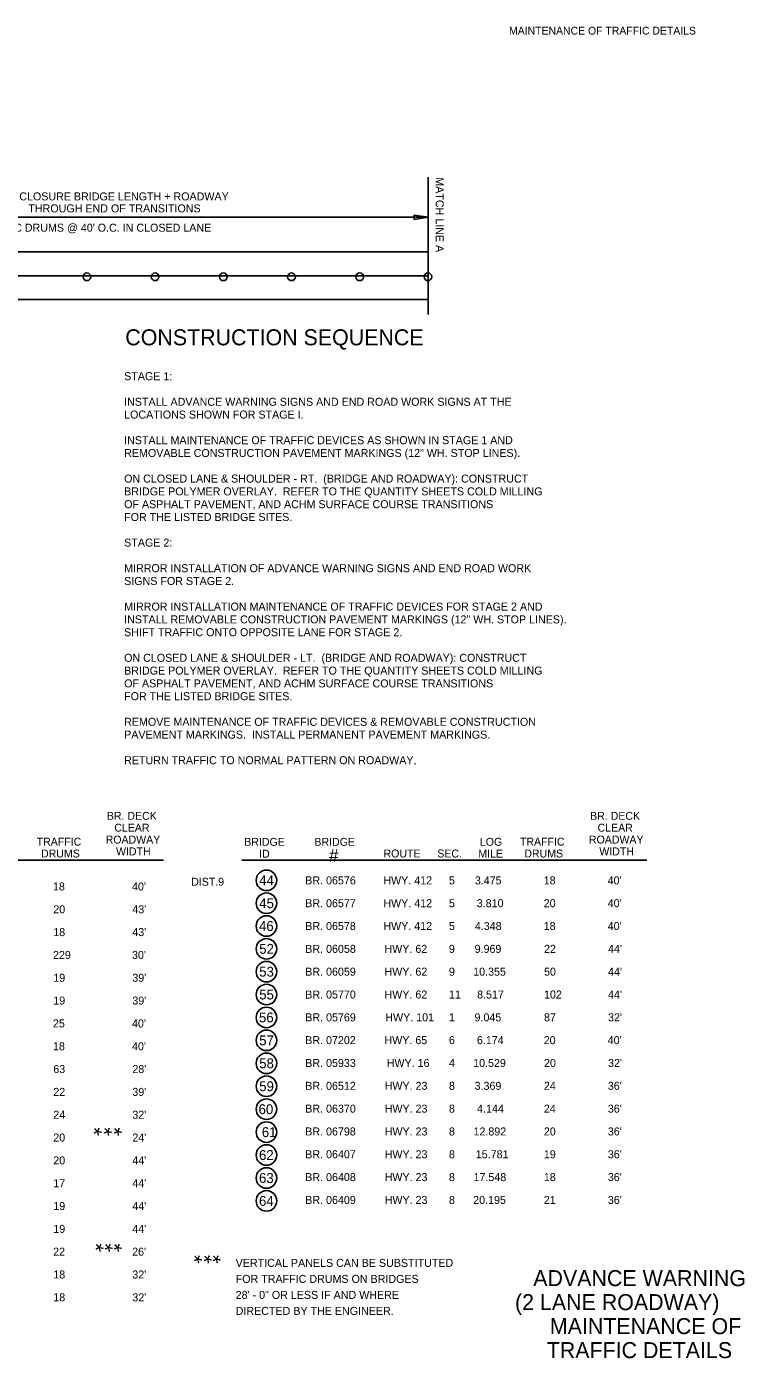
# Model space of a CAD drawing. Extents: x 1927831 to 1930787, y 596452 to 597699.
# Drawn here: x 1928872 to 1929411, y 596676 to 597675 of the extents above; entities that cross this region are included whole.
import ezdxf

# ---------------------------------------------------------------- set-up
doc = ezdxf.new("R2010")
doc.units = 0
for name, color, linetype in [('Default', 7, 'Continuous'), ('R_Border', 7, 'Continuous'), ('S_AREA_CALC', 7, 'Continuous')]:
    doc.layers.add(name, color=color, linetype=linetype)

msp = doc.modelspace()

# ---------------------------------------------------------------- linework, layer by layer
at = {"layer": 'Default'}
for p, q in [((1929173.7, 597561.58), (1929173.7, 597458.57)), ((1929173.7, 597531.57), (1928729.31, 597531.57)), ((1929163.15, 597529.98), (1929163.15, 597533.15)), ((1929163.15, 597533.15), (1929173.7, 597531.57)), ((1929173.7, 597531.57), (1929163.15, 597529.98)), ((1928044.85, 597505.58), (1929173.7, 597505.58)), ((1927908.3, 597487.79), (1929173.7, 597487.79)), ((1928044.85, 597470), (1929173.7, 597470))]:
    msp.add_line(p, q, dxfattribs=at)
for centre, radius in [((1928917.66, 597486.95), 2.88), ((1928968.83, 597486.95), 2.88), ((1929019.99, 597486.95), 2.88), ((1929071.15, 597486.95), 2.88), ((1929122.31, 597486.95), 2.88), ((1929173.48, 597486.95), 2.88), ((1929052.37, 597034.32), 7.71), ((1929052.37, 597017.2), 7.71), ((1929052.37, 597000.08), 7.71), ((1929052.37, 596982.96), 7.71), ((1929052.37, 596965.85), 7.71), ((1929052.37, 596948.73), 7.71), ((1929052.37, 596931.53), 7.71), ((1929052.37, 596914.33), 7.71), ((1929052.37, 596897.13), 7.71), ((1929052.37, 596879.93), 7.71), ((1929052.37, 596862.73), 7.71), ((1929052.37, 596845.53), 7.71), ((1929052.37, 596828.33), 7.71), ((1929052.37, 596811.13), 7.71), ((1929052.37, 596793.93), 7.71)]:
    msp.add_circle(centre, radius, dxfattribs=at)
at = {"layer": 'R_Border'}
for p, q in [((1928671.26, 597049.57), (1928975.19, 597049.57)), ((1929033.81, 597049.57), (1929337.74, 597049.57))]:
    msp.add_line(p, q, dxfattribs=at)

# ---------------------------------------------------------------- texts
at = {"layer": 'Default'}
for s, height, rotation, p in [('MATCH LINE A', 6, 270, (1929179.33, 597561.58)), ('LANE CLOSURE BRIDGE LENGTH + ROADWAY ', 5.9996, 360, (1928843.74, 597544.26)), ('THROUGH END OF TRANSITIONS', 5.9996, 360, (1928873.73, 597535.26)), ("TRAFFIC DRUMS @ 40' O.C. IN CLOSED LANE", 5.9996, 360, (1928835.01, 597520.77))]:
    msp.add_text(s, height=height, rotation=rotation, dxfattribs=at).set_placement(p)
at = {"layer": 'R_Border'}
for s, height, rotation, p in [('CONSTRUCTION SEQUENCE', 12, 360, (1928946.46, 597435.58)), ('STAGE 1:', 6, 360, (1928945.6, 597409.43)), ('INSTALL ADVANCE WARNING SIGNS AND END ROAD WORK SIGNS AT THE', 6, 360, (1928945.6, 597390.23)), ('LOCATIONS SHOWN FOR STAGE I.  ', 6, 360, (1928945.6, 597380.63)), ('INSTALL MAINTENANCE OF TRAFFIC DEVICES AS SHOWN IN STAGE 1 AND', 6, 360, (1928945.6, 597361.43)), ('REMOVABLE CONSTRUCTION PAVEMENT MARKINGS (12" WH. STOP LINES). ', 6, 360, (1928945.6, 597351.83)), ('ON CLOSED LANE & SHOULDER - RT.  (BRIDGE AND ROADWAY): CONSTRUCT', 6, 360, (1928945.6, 597332.63)), ('BRIDGE POLYMER OVERLAY.  REFER TO THE QUANTITY SHEETS COLD MILLING', 6, 360, (1928945.6, 597323.03)), ('OF ASPHALT PAVEMENT, AND ACHM SURFACE COURSE TRANSITIONS', 6, 360, (1928945.6, 597313.43)), ('FOR THE LISTED BRIDGE SITES.', 6, 360, (1928945.6, 597303.83)), ('STAGE 2:', 6, 360, (1928945.6, 597284.63)), ('MIRROR INSTALLATION OF ADVANCE WARNING SIGNS AND END ROAD WORK', 6, 360, (1928945.6, 597265.43)), ('SIGNS FOR STAGE 2.  ', 6, 360, (1928945.6, 597255.83)), ('MIRROR INSTALLATION MAINTENANCE OF TRAFFIC DEVICES FOR STAGE 2 AND', 6, 360, (1928945.6, 597236.63)), ('INSTALL REMOVABLE CONSTRUCTION PAVEMENT MARKINGS (12" WH. STOP LINES).', 6, 360, (1928945.6, 597227.03)), ('SHIFT TRAFFIC ONTO OPPOSITE LANE FOR STAGE 2.', 6, 360, (1928945.6, 597217.43)), ('ON CLOSED LANE & SHOULDER - LT.  (BRIDGE AND ROADWAY): CONSTRUCT', 6, 360, (1928945.6, 597198.23)), ('BRIDGE POLYMER OVERLAY.  REFER TO THE QUANTITY SHEETS COLD MILLING', 6, 360, (1928945.6, 597188.63)), ('OF ASPHALT PAVEMENT, AND ACHM SURFACE COURSE TRANSITIONS', 6, 360, (1928945.6, 597179.03)), ('FOR THE LISTED BRIDGE SITES.', 6, 360, (1928945.6, 597169.43)), ('REMOVE MAINTENANCE OF TRAFFIC DEVICES & REMOVABLE CONSTRUCTION', 6, 360, (1928945.6, 597150.23)), ('PAVEMENT MARKINGS.  INSTALL PERMANENT PAVEMENT MARKINGS.', 6, 360, (1928945.6, 597140.63)), ('RETURN TRAFFIC TO NORMAL PATTERN ON ROADWAY. ', 6, 360, (1928945.6, 597121.43)), ('BR. DECK ', 5.929, 360, (1928932.62, 597079.75)), ('BR. DECK ', 5.929, 360, (1929295.17, 597079.75)), ('CLEAR', 5.929, 360, (1928938.2, 597070.86)), ('CLEAR', 5.929, 360, (1929300.75, 597070.86)), ('TRAFFIC ', 5.929, 360, (1928879.98, 597060.4)), ('ROADWAY ', 5.929, 360, (1928931.73, 597061.96)), ('BRIDGE ', 5.929, 360, (1929035.7, 597060.24)), ('BRIDGE ', 5.929, 360, (1929088.33, 597060.24)), ('LOG', 5.929, 360, (1929212.52, 597060.28)), ('TRAFFIC ', 5.929, 360, (1929242.53, 597060.4)), ('ROADWAY ', 5.929, 360, (1929294.28, 597061.96)), ('DRUMS', 5.929, 360, (1928883.27, 597051.51)), ('WIDTH', 5.929, 360, (1928939.53, 597053.07)), ('ID', 5.929, 360, (1929046.88, 597051.35)), ('#', 9.5, 360, (1929099.32, 597048.38)), ('ROUTE', 5.929, 360, (1929140.18, 597051.51)), ('SEC.', 5.929, 360, (1929180.51, 597051.51)), ('MILE', 5.929, 360, (1929211.29, 597051.39)), ('DRUMS', 5.929, 360, (1929245.82, 597051.51)), ('WIDTH', 5.929, 360, (1929302.08, 597053.07)), ('DIST.9', 5.929, 360, (1928995.9, 597030.33)), ('44', 7.412, 360, (1929046.94, 597030.61)), ('BR. 06576', 6, 360, (1929081.46, 597031.32)), ('HWY. 412', 6, 360, (1929140.05, 597031.32)), ('5', 6, 360, (1929189.24, 597031.32)), ('3.475', 6, 360, (1929208.68, 597031.32)), ('18', 6, 360, (1929260.35, 597031.32)), ("40'", 6, 360, (1929308.35, 597031.32)), ('18', 6, 360, (1928892.21, 597026.76)), ("40'", 6, 360, (1928951.51, 597026.76)), ('20', 6, 360, (1928892.45, 597009.64)), ("43'", 6, 360, (1928951.74, 597009.64)), ('45', 7.412, 360, (1929046.94, 597013.49)), ('BR. 06577', 6, 360, (1929081.46, 597014.2)), ('HWY. 412', 6, 360, (1929140.05, 597014.2)), ('5', 6, 360, (1929189.24, 597014.2)), ('3.810', 6, 360, (1929210.12, 597014.2)), ('20', 6, 360, (1929260.35, 597014.2)), ("40'", 6, 360, (1929308.35, 597014.2)), ('18', 6, 360, (1928892.45, 596992.52)), ("43'", 6, 360, (1928951.74, 596992.52)), ('46', 7.412, 360, (1929046.74, 596996.38)), ('BR. 06578', 6, 360, (1929081.46, 596997.08)), ('HWY. 412', 6, 360, (1929140.05, 596997.08)), ('5', 6, 360, (1929189.24, 596997.08)), ('4.348', 6, 360, (1929208.68, 596997.08)), ('18', 6, 360, (1929260.35, 596997.08)), ("40'", 6, 360, (1929308.35, 596997.08)), ('52', 7.412, 360, (1929046.94, 596979.26)), ('BR. 06058', 6, 360, (1929081.46, 596979.96)), ('HWY. 62', 6, 360, (1929140.9, 596979.96)), ('9', 6, 360, (1929189.24, 596979.96)), ('9.969', 6, 360, (1929208.51, 596979.96)), ('22', 6, 360, (1929260.59, 596979.96)), ("44'", 6, 360, (1929308.59, 596979.96)), ('229', 6, 360, (1928892.21, 596975.41)), ("30'", 6, 360, (1928951.51, 596975.41)), ('53', 7.412, 360, (1929046.94, 596962.14)), ('BR. 06059', 6, 360, (1929081.46, 596962.85)), ('HWY. 62', 6, 360, (1929140.9, 596962.85)), ('9', 6, 360, (1929189.24, 596962.85)), ('10.355', 6, 360, (1929207.45, 596962.85)), ('50', 6, 360, (1929260.59, 596962.85)), ("44'", 6, 360, (1929308.59, 596962.85)), ('19', 6, 360, (1928892.45, 596958.29)), ("39'", 6, 360, (1928951.74, 596958.29)), ('19', 6, 360, (1928892.45, 596941.17)), ("39'", 6, 360, (1928951.74, 596941.17)), ('55', 7.412, 360, (1929046.94, 596945.02)), ('BR. 05770', 6, 360, (1929081.46, 596945.73)), ('HWY. 62', 6, 360, (1929140.9, 596945.73)), ('11', 6, 360, (1929189.24, 596945.73)), ('8.517', 6, 360, (1929210.38, 596945.73)), ('102', 6, 360, (1929260.59, 596945.73)), ("44'", 6, 360, (1929308.59, 596945.73)), ('25', 6, 360, (1928892.21, 596924.05)), ("40'", 6, 360, (1928951.51, 596924.05)), ('56', 7.412, 360, (1929046.74, 596927.82)), ('BR. 05769', 6, 360, (1929081.46, 596928.61)), ('HWY. 101', 6, 360, (1929141.51, 596928.61)), ('1', 6, 360, (1929189.24, 596928.61)), ('9.045', 6, 360, (1929208.44, 596928.61)), ('87', 6, 360, (1929260.59, 596928.61)), ("32'", 6, 360, (1929308.59, 596928.61)), ('57', 7.412, 360, (1929046.94, 596910.62)), ('BR. 07202', 6, 360, (1929081.46, 596911.49)), ('HWY. 65', 6, 360, (1929140.9, 596911.49)), ('6', 6, 360, (1929189.24, 596911.49)), ('6.174', 6, 360, (1929210.24, 596911.49)), ('20', 6, 360, (1929260.35, 596911.49)), ("40'", 6, 360, (1929308.35, 596911.49)), ('18', 6, 360, (1928892.21, 596906.93)), ("40'", 6, 360, (1928951.51, 596906.93)), ('63', 6, 360, (1928892.45, 596889.82)), ("28'", 6, 360, (1928951.74, 596889.82)), ('58', 7.412, 360, (1929046.94, 596893.42)), ('BR. 05933', 6, 360, (1929081.46, 596894.38)), ('HWY. 16', 6, 360, (1929142.58, 596894.38)), ('4', 6, 360, (1929189.24, 596894.38)), ('10.529', 6, 360, (1929207.43, 596894.38)), ('20', 6, 360, (1929260.59, 596894.38)), ("32'", 6, 360, (1929308.59, 596894.38)), ('22', 6, 360, (1928892.45, 596872.7)), ("39'", 6, 360, (1928951.74, 596872.7)), ('59', 7.412, 360, (1929046.91, 596876.22)), ('BR. 06512', 6, 360, (1929081.46, 596877.26)), ('HWY. 23', 6, 360, (1929141.04, 596877.26)), ('8', 6, 360, (1929189.24, 596877.26)), ('3.369', 6, 360, (1929208.51, 596877.26)), ('24', 6, 360, (1929260.45, 596877.26)), ("36'", 6, 360, (1929308.45, 596877.26)), ('60', 7.412, 360, (1929046.45, 596859.02)), ('BR. 06370', 6, 360, (1929081.46, 596860.14)), ('HWY. 23', 6, 360, (1929141.04, 596860.14)), ('8', 6, 360, (1929189.24, 596860.14)), ('4.144', 6, 360, (1929210.38, 596860.14)), ('24', 6, 360, (1929260.45, 596860.14)), ("36'", 6, 360, (1929308.45, 596860.14)), ('24', 6, 360, (1928892.45, 596855.58)), ("32'", 6, 360, (1928951.74, 596855.58)), ('*', 12, 45, (1928929.66, 596837.55)), ('*', 12, 45, (1928937.34, 596837.55)), ('*', 12, 45, (1928944.78, 596837.55)), ('61', 7.412, 360, (1929048.87, 596841.82)), ('BR. 06798', 6, 360, (1929081.46, 596843.02)), ('HWY. 23', 6, 360, (1929141.04, 596843.02)), ('8', 6, 360, (1929189.24, 596843.02)), ('12.892', 6, 360, (1929207.69, 596843.02)), ('20', 6, 360, (1929260.45, 596843.02)), ("36'", 6, 360, (1929308.45, 596843.02)), ('20', 6, 360, (1928892.45, 596838.46)), ("24'", 6, 360, (1928951.74, 596838.46)), ('20', 6, 360, (1928892.45, 596821.35)), ("44'", 6, 360, (1928951.74, 596821.35)), ('62', 7.412, 360, (1929046.77, 596824.62)), ('BR. 06407', 6, 360, (1929081.46, 596825.91)), ('HWY. 23', 6, 360, (1929141.04, 596825.91)), ('8', 6, 360, (1929189.24, 596825.91)), ('15.781', 6, 360, (1929209.39, 596825.91)), ('19', 6, 360, (1929260.45, 596825.91)), ("36'", 6, 360, (1929308.45, 596825.91)), ('17', 6, 360, (1928892.45, 596804.23)), ("44'", 6, 360, (1928951.74, 596804.23)), ('63', 7.412, 360, (1929046.77, 596807.42)), ('BR. 06408', 6, 360, (1929081.46, 596808.79)), ('HWY. 23', 6, 360, (1929141.04, 596808.79)), ('8', 6, 360, (1929189.24, 596808.79)), ('17.548', 6, 360, (1929207.69, 596808.79)), ('18', 6, 360, (1929260.45, 596808.79)), ("36'", 6, 360, (1929308.45, 596808.79)), ('64', 7.412, 360, (1929046.77, 596790.22)), ('BR. 06409', 6, 360, (1929081.46, 596791.67)), ('HWY. 23', 6, 360, (1929141.04, 596791.67)), ('8', 6, 360, (1929189.24, 596791.67)), ('20.195', 6, 360, (1929207.45, 596791.67)), ('21', 6, 360, (1929260.45, 596791.67)), ("36'", 6, 360, (1929308.45, 596791.67)), ('19', 6, 360, (1928892.45, 596787.11)), ("44'", 6, 360, (1928951.74, 596787.11)), ('19', 6, 360, (1928892.45, 596769.99)), ("44'", 6, 360, (1928951.74, 596769.99)), ('22', 6, 360, (1928892.31, 596752.88)), ('*', 12, 45, (1928931.02, 596750.51)), ('*', 12, 45, (1928937.97, 596750.51)), ('*', 12, 45, (1928944.78, 596750.51)), ("26'", 6, 360, (1928951.6, 596752.88)), ('*', 12, 45, (1929004.86, 596741.85)), ('*', 12, 45, (1929012.28, 596741.85)), ('*', 12, 45, (1929018.89, 596741.85)), ('VERTICAL PANELS CAN BE SUBSTITUTED ', 6, 360, (1929029.27, 596744.45)), ('18', 6, 360, (1928892.45, 596735.76)), ("32'", 6, 360, (1928951.74, 596735.76)), ('FOR TRAFFIC DRUMS ON BRIDGES ', 6, 360, (1929029.27, 596732.45)), ('ADVANCE WARNING', 12, 360, (1929252.49, 596730.03)), ('28\' - 0" OR LESS IF AND WHERE ', 6, 360, (1929029.27, 596720.45)), ('18', 6, 360, (1928892.45, 596718.64)), ("32'", 6, 360, (1928951.74, 596718.64)), (' (2 LANE ROADWAY) ', 12, 360, (1929234.35, 596712.03)), ('DIRECTED BY THE ENGINEER.', 6, 360, (1929029.27, 596708.45)), ('MAINTENANCE OF ', 12, 360, (1929264.96, 596694.03)), ('TRAFFIC DETAILS', 12, 360, (1929262.6, 596676.03))]:
    msp.add_text(s, height=height, rotation=rotation, dxfattribs=at).set_placement(p)
at = {"layer": 'S_AREA_CALC'}
msp.add_text('MAINTENANCE OF TRAFFIC DETAILS', height=5.862, rotation=360, dxfattribs=at).set_placement((1929234.33, 597668.61))

doc.saveas('drawing.dxf')
